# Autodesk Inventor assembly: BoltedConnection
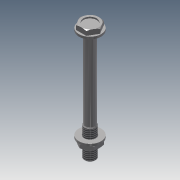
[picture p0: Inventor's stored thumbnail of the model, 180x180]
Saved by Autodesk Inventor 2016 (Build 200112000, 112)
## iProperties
Created: 2013-11
Part Number: BoltedConnection
Document SubType Name: Assembly
Designer: normanpa
Author: normanpa
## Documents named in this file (4)
- C:\_P4_Inv_R20QA\inventor\streams\Shelby\R20QA\PSS\InteractiveTutorial\Drawing_3\TutorialModelPath\Pump_Components\BoltedConnection.iam
- C:\_P4_Inv_R20QA\inventor\streams\Shelby\R20QA\PSS\InteractiveTutorial\Drawing_3\TutorialModelPath\Pump_Components\ISO 4015 - M10 x 100.ipt
- C:\_P4_Inv_R20QA\inventor\streams\Shelby\R20QA\PSS\InteractiveTutorial\Drawing_3\TutorialModelPath\Pump_Components\ISO 4035 - M10ISO.ipt
- C:\_P4_Inv_R20QA\inventor\streams\Shelby\R20QA\PSS\InteractiveTutorial\Drawing_3\TutorialModelPath\Pump_Components\ISO 7089 - 10 - 140 HV.ipt
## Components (4 placed, 3 different names)
1. ISO 4015 M10 x 100:1
2. ISO 4035 M10:1
3. ISO 7089 10 - 140 HV:1
4. ISO 7089 10 - 140 HV:2
